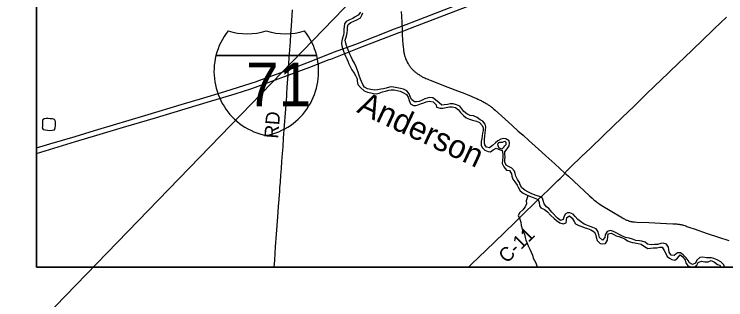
# Model space of a CAD drawing. Extents: x -49 to -8.2, y 9.4 to 23.5.
# Drawn here: x -46.335 to -44.886, y 14.138 to 14.718 of the extents above; entities that cross this region are included whole.
import ezdxf

# ---------------------------------------------------------------- set-up
doc = ezdxf.new("R2010")
doc.units = 0
for name, color, linetype in [('GM_X_Adjacent_County', 7, 'Continuous'), ('GM_X_County_Road', 7, 'Continuous'), ('GM_X_County_Road_Text', 7, 'Continuous'), ('GM_X_Interstate_Route', 7, 'Continuous'), ('GM_X_Interstate_Shield', 7, 'Continuous'), ('GM_X_Major_River', 7, 'Continuous'), ('GM_X_Major_River_Text', 7, 'Continuous'), ('GM_X_Minor_Lake', 7, 'Continuous'), ('GM_X_Minor_River', 7, 'Continuous'), ('GM_X_Township', 7, 'Continuous'), ('GM_X_Township_Road', 7, 'Continuous'), ('GM_X_Township_Road_Text', 7, 'Continuous'), ('SC_Scratch1', 7, 'Continuous')]:
    doc.layers.add(name, color=color, linetype=linetype)

msp = doc.modelspace()

# ---------------------------------------------------------------- linework, layer by layer
at = {"layer": 'GM_X_Adjacent_County'}
msp.add_lwpolyline([(-39.4895, 17.0861), (-39.4895, 14.2039), (-46.2895, 14.2039), (-46.2895, 15.4273)], dxfattribs=at)
at = {"layer": 'GM_X_County_Road'}
for points in [[(-45.5468, 14.7238), (-45.5464, 14.7141), (-45.5458, 14.7024), (-45.5453, 14.6944), (-45.5451, 14.6903), (-45.5447, 14.6835), (-45.5445, 14.6772), (-45.5439, 14.6664), (-45.5438, 14.6632), (-45.5436, 14.6604), (-45.5433, 14.6566), (-45.543, 14.6534), (-45.5427, 14.6505), (-45.5424, 14.6479), (-45.5422, 14.646), (-45.5419, 14.644), (-45.5416, 14.6421), (-45.5413, 14.6404), (-45.541, 14.6388), (-45.5406, 14.6373), (-45.5402, 14.6356), (-45.5398, 14.6341), (-45.5392, 14.6322), (-45.5387, 14.6308), (-45.5383, 14.6296), (-45.5377, 14.6279), (-45.5371, 14.6264), (-45.5363, 14.6246), (-45.5355, 14.6229), (-45.5346, 14.6211), (-45.5336, 14.6193), (-45.5327, 14.6177), (-45.532, 14.6167), (-45.5313, 14.6156), (-45.5303, 14.6141), (-45.5293, 14.6128), (-45.5282, 14.6113), (-45.5272, 14.61), (-45.5262, 14.6087), (-45.525, 14.6074), (-45.5241, 14.6064), (-45.5231, 14.6054), (-45.5221, 14.6043), (-45.521, 14.6033), (-45.52, 14.6023), (-45.5189, 14.6014), (-45.5178, 14.6005), (-45.5166, 14.5995), (-45.5151, 14.5984), (-45.5136, 14.5973), (-45.5122, 14.5964), (-45.511, 14.5956), (-45.5098, 14.5948), (-45.5085, 14.594), (-45.5071, 14.5932), (-45.5054, 14.5922), (-45.5038, 14.5913), (-45.5024, 14.5906), (-45.5007, 14.5897), (-45.4988, 14.5888), (-45.4964, 14.5878), (-45.494, 14.5868), (-45.4914, 14.5857), (-45.4881, 14.5844), (-45.4724, 14.5782), (-45.4605, 14.5736), (-45.4373, 14.5647), (-45.4174, 14.5569), (-45.4112, 14.5544), (-45.4059, 14.5523), (-45.4017, 14.5506), (-45.3995, 14.5497), (-45.397, 14.5486), (-45.3949, 14.5477), (-45.3928, 14.5468), (-45.3907, 14.5458), (-45.3891, 14.5451), (-45.3877, 14.5444), (-45.3861, 14.5436), (-45.3842, 14.5426), (-45.3825, 14.5417), (-45.3805, 14.5406), (-45.3783, 14.5394), (-45.3761, 14.5382), (-45.3741, 14.537), (-45.3725, 14.5361), (-45.3711, 14.5352), (-45.3696, 14.5343), (-45.3683, 14.5334), (-45.367, 14.5325), (-45.3658, 14.5317), (-45.3642, 14.5305), (-45.3629, 14.5295), (-45.3616, 14.5285), (-45.3601, 14.5273), (-45.3579, 14.5255), (-45.3556, 14.5235), (-45.3356, 14.5053), (-45.3204, 14.4916), (-45.3091, 14.4814), (-45.2986, 14.4721), (-45.2866, 14.4613), (-45.2742, 14.45), (-45.2606, 14.4377), (-45.2522, 14.4303), (-45.2343, 14.414), (-45.2133, 14.3952)], [(-45.2133, 14.3952), (-45.2127, 14.3959), (-45.2122, 14.3966), (-45.2115, 14.3975), (-45.2108, 14.3983), (-45.2101, 14.3991), (-45.2089, 14.4004), (-45.2074, 14.4018), (-45.2056, 14.4037), (-45.2018, 14.4074), (-45.1787, 14.4296), (-45.162, 14.4455), (-45.1348, 14.4718), (-45.0972, 14.508), (-45.0725, 14.5317), (-45.047, 14.5563), (-45.0314, 14.5714), (-45.0025, 14.5992), (-44.9805, 14.6203), (-44.9723, 14.6283), (-44.9518, 14.6482), (-44.9354, 14.6639), (-44.9101, 14.6882), (-44.896, 14.7018), (-44.8845, 14.7126)], [(-45.4097, 14.2039), (-45.4043, 14.2091), (-45.3872, 14.2258), (-45.3751, 14.2374), (-45.3549, 14.2568), (-45.3384, 14.2727), (-45.3299, 14.281), (-45.3224, 14.2883), (-45.315, 14.2955), (-45.3044, 14.3059), (-45.2907, 14.3191), (-45.2814, 14.3282), (-45.2735, 14.3359), (-45.2694, 14.34), (-45.2657, 14.3436), (-45.2624, 14.3467), (-45.2591, 14.3499), (-45.2554, 14.3534), (-45.2499, 14.3587), (-45.2365, 14.3716), (-45.2277, 14.38), (-45.2233, 14.3842), (-45.2205, 14.3868), (-45.219, 14.3884), (-45.2173, 14.3901), (-45.2165, 14.391), (-45.2157, 14.392), (-45.2149, 14.3929), (-45.2141, 14.394), (-45.2133, 14.3952)], [(-45.2133, 14.3952), (-45.211, 14.3931), (-45.2062, 14.3888), (-45.1956, 14.379), (-45.1634, 14.3491), (-45.1578, 14.3441), (-45.1544, 14.341), (-45.1523, 14.3393), (-45.1501, 14.3375), (-45.1484, 14.3361), (-45.1464, 14.3346), (-45.1445, 14.3333), (-45.1426, 14.3319), (-45.1399, 14.3302), (-45.1364, 14.3281), (-45.1214, 14.3193), (-45.0965, 14.3045), (-45.0941, 14.3032), (-45.0921, 14.302), (-45.0907, 14.3012), (-45.0893, 14.3005), (-45.0878, 14.2998), (-45.0866, 14.2992), (-45.085, 14.2986), (-45.0837, 14.2981), (-45.0828, 14.2977), (-45.0816, 14.2973), (-45.0802, 14.297), (-45.079, 14.2968), (-45.0774, 14.2965), (-45.0759, 14.2963), (-45.0737, 14.2961), (-45.0715, 14.2959), (-45.0671, 14.2957), (-45.0425, 14.2945), (-45.0066, 14.2929), (-44.9938, 14.2924), (-44.992, 14.2923), (-44.9901, 14.2922), (-44.9883, 14.2921), (-44.986, 14.2919), (-44.9839, 14.2917), (-44.9821, 14.2915), (-44.9807, 14.2913), (-44.9795, 14.291), (-44.9784, 14.2908), (-44.9769, 14.2905), (-44.9752, 14.2901), (-44.9738, 14.2897), (-44.972, 14.2892), (-44.9695, 14.2884), (-44.9674, 14.2877), (-44.965, 14.2869), (-44.9588, 14.2848), (-44.9505, 14.2819), (-44.9236, 14.2724), (-44.9005, 14.2647), (-44.8794, 14.258)]]:
    msp.add_lwpolyline(points, dxfattribs=at)
at = {"layer": 'GM_X_Interstate_Route'}
for points in [[(-45.6199, 14.6545), (-45.5512, 14.6809), (-45.5447, 14.6835), (-45.5277, 14.6902), (-45.4354, 14.7255), (-45.3554, 14.7563), (-45.2574, 14.7941), (-45.2, 14.8162), (-45.1231, 14.8457), (-45.0115, 14.8888), (-44.9338, 14.9187), (-44.8808, 14.9391), (-44.8112, 14.9659)], [(-46.2895, 14.4464), (-46.262, 14.4547), (-46.2104, 14.47), (-46.1712, 14.4818), (-46.1645, 14.484), (-46.1009, 14.5028), (-46.0687, 14.5123), (-45.9879, 14.5368), (-45.9554, 14.5464), (-45.906, 14.5611), (-45.8653, 14.5739), (-45.8414, 14.5817), (-45.8364, 14.5833), (-45.8078, 14.5937), (-45.7762, 14.6056), (-45.7264, 14.6245), (-45.6845, 14.641), (-45.6394, 14.6578), (-45.5604, 14.6886), (-45.5453, 14.6944), (-45.4293, 14.7391)], [(-45.6903, 14.6273), (-45.6324, 14.6497), (-45.6199, 14.6545)], [(-46.2895, 14.4353), (-46.2631, 14.4432), (-46.2096, 14.4592), (-46.1667, 14.4721), (-46.1122, 14.4884), (-46.0473, 14.5078), (-45.942, 14.5393), (-45.8846, 14.5567), (-45.8512, 14.5675), (-45.8251, 14.5766), (-45.8099, 14.5821), (-45.7769, 14.5941), (-45.7325, 14.6109), (-45.6932, 14.6262), (-45.6903, 14.6273)]]:
    msp.add_lwpolyline(points, dxfattribs=at)
at = {"layer": 'GM_X_Interstate_Shield'}
for p, q in [((-45.9239, 14.6345), (-45.7189, 14.6345)), ((-45.7189, 14.6345), (-45.9239, 14.6345)), ((-45.7189, 14.6345), (-45.9239, 14.6345))]:
    msp.add_line(p, q, dxfattribs=at)
for centre, start, end in [((-45.7947, 14.6019), 141.669, 165.8066), ((-45.8603, 14.8118), 253.0091, 286.9909), ((-45.7825, 14.8118), 253.0091, 286.9909), ((-45.848, 14.6019), 14.1934, 38.331), ((-45.7947, 14.6019), 165.8066, 258.463), ((-45.848, 14.6019), 281.537, 14.1934)]:
    msp.add_arc(centre, 0.1332, start, end, dxfattribs=at)
at = {"layer": 'GM_X_Major_River'}
for points in [[(-45.6296, 14.7227), (-45.6345, 14.7165), (-45.6402, 14.7131), (-45.6455, 14.71), (-45.6523, 14.707), (-45.6588, 14.7038), (-45.6622, 14.6987), (-45.6628, 14.6926), (-45.6634, 14.6879), (-45.6638, 14.6812), (-45.6643, 14.6757), (-45.666, 14.6704), (-45.6674, 14.6645), (-45.6682, 14.659), (-45.6678, 14.6543), (-45.6661, 14.6492), (-45.6642, 14.6431), (-45.6623, 14.6376), (-45.6602, 14.6329), (-45.6574, 14.6274), (-45.6555, 14.6226), (-45.6531, 14.6173), (-45.6501, 14.6108), (-45.6476, 14.605), (-45.6425, 14.5985), (-45.6397, 14.5938), (-45.6366, 14.5869), (-45.6363, 14.582), (-45.6351, 14.5757), (-45.6293, 14.5695), (-45.6223, 14.5626), (-45.6153, 14.5598), (-45.6088, 14.5583), (-45.603, 14.5573), (-45.5963, 14.5563), (-45.5914, 14.558), (-45.585, 14.5605), (-45.5785, 14.5616), (-45.5721, 14.5637), (-45.5673, 14.5646), (-45.5611, 14.5643), (-45.555, 14.5635), (-45.5486, 14.5616), (-45.5433, 14.5593), (-45.5363, 14.5549), (-45.5329, 14.55), (-45.5308, 14.5428)], [(-45.3771, 14.464), (-45.3767, 14.4703), (-45.3756, 14.4769), (-45.3752, 14.4828), (-45.3743, 14.4894), (-45.3756, 14.4949), (-45.3807, 14.5012), (-45.3858, 14.5033), (-45.3918, 14.5086), (-45.3994, 14.5115), (-45.4064, 14.5122), (-45.4129, 14.5157), (-45.4195, 14.5204), (-45.4231, 14.5261), (-45.4274, 14.5314), (-45.4342, 14.5339), (-45.4409, 14.5364), (-45.4469, 14.5358), (-45.4528, 14.5345), (-45.459, 14.5338), (-45.4638, 14.5332), (-45.4698, 14.5379), (-45.4766, 14.544), (-45.4825, 14.5484), (-45.4888, 14.5488), (-45.4939, 14.5478), (-45.4986, 14.5463), (-45.5039, 14.5437), (-45.5104, 14.5412), (-45.5153, 14.5403), (-45.52, 14.5399), (-45.5255, 14.5452), (-45.5283, 14.5513), (-45.5306, 14.5562), (-45.5353, 14.5623), (-45.5418, 14.5661), (-45.5482, 14.5676), (-45.5548, 14.5684), (-45.5658, 14.5707), (-45.5707, 14.5701), (-45.5772, 14.5681), (-45.5829, 14.5668), (-45.588, 14.5662), (-45.5952, 14.5647), (-45.6014, 14.5641), (-45.6083, 14.5655), (-45.6153, 14.5666), (-45.6215, 14.5698), (-45.6251, 14.5757), (-45.6279, 14.5818), (-45.6296, 14.5865), (-45.6323, 14.5936), (-45.6345, 14.6004), (-45.6364, 14.6057), (-45.6385, 14.6116), (-45.6421, 14.6188), (-45.6457, 14.6254), (-45.6487, 14.6317), (-45.6511, 14.637), (-45.6532, 14.6423), (-45.656, 14.6494), (-45.6581, 14.6549), (-45.6598, 14.6596), (-45.6606, 14.6657), (-45.6583, 14.6736), (-45.6566, 14.6805), (-45.6562, 14.6863), (-45.6563, 14.6926), (-45.6548, 14.6973), (-45.6495, 14.7017), (-45.6431, 14.7043), (-45.6368, 14.7072), (-45.6294, 14.7113), (-45.6271, 14.7164), (-45.625, 14.7214)], [(-45.5308, 14.5428), (-45.528, 14.5363), (-45.5217, 14.5325), (-45.517, 14.5325), (-45.5121, 14.5338), (-45.5056, 14.5369), (-45.5009, 14.5382), (-45.496, 14.5399), (-45.489, 14.5414), (-45.4816, 14.5402), (-45.4757, 14.5343), (-45.4746, 14.5296), (-45.4676, 14.5273), (-45.4619, 14.5271), (-45.4553, 14.5284), (-45.4484, 14.5303), (-45.4431, 14.5303), (-45.4365, 14.5286), (-45.4303, 14.5242), (-45.4261, 14.5187), (-45.4202, 14.5121), (-45.4144, 14.5077), (-45.4079, 14.5049), (-45.4013, 14.5029), (-45.3936, 14.5007), (-45.3871, 14.498), (-45.3818, 14.4921), (-45.3799, 14.4874), (-45.3801, 14.4822), (-45.3811, 14.4762), (-45.3819, 14.4712), (-45.3826, 14.4659), (-45.3838, 14.4593), (-45.384, 14.4521), (-45.3817, 14.4474), (-45.3762, 14.4417), (-45.37, 14.439), (-45.3652, 14.4384), (-45.3592, 14.4428), (-45.3533, 14.4458), (-45.3472, 14.4431), (-45.341, 14.441), (-45.3395, 14.4344), (-45.3399, 14.4283), (-45.3405, 14.4215), (-45.3409, 14.4147), (-45.3378, 14.4078), (-45.3322, 14.4014), (-45.3261, 14.4002), (-45.3219, 14.3938), (-45.3216, 14.3889), (-45.3193, 14.3826), (-45.3153, 14.3777), (-45.3104, 14.371), (-45.3078, 14.3653), (-45.3046, 14.3591), (-45.2987, 14.3543), (-45.293, 14.3518), (-45.2872, 14.349), (-45.2817, 14.3467), (-45.2749, 14.3444), (-45.2682, 14.3416), (-45.2658, 14.3353), (-45.265, 14.329), (-45.2622, 14.3243), (-45.255, 14.3211), (-45.2488, 14.3163), (-45.2431, 14.31), (-45.2355, 14.303), (-45.2306, 14.299), (-45.2238, 14.2941), (-45.2168, 14.2918), (-45.2111, 14.2941), (-45.2103, 14.2992), (-45.2098, 14.3051), (-45.2039, 14.3081), (-45.1986, 14.3033), (-45.1946, 14.2969), (-45.1916, 14.2921), (-45.1848, 14.2887), (-45.1793, 14.2864), (-45.174, 14.2847), (-45.1677, 14.2828), (-45.1604, 14.2798), (-45.1537, 14.276), (-45.1509, 14.2712), (-45.1496, 14.265), (-45.1477, 14.2581), (-45.1418, 14.2522), (-45.1364, 14.2511), (-45.1309, 14.252), (-45.1265, 14.2587), (-45.1261, 14.2653), (-45.1251, 14.2716), (-45.1196, 14.2731), (-45.114, 14.2702), (-45.1089, 14.2679), (-45.1036, 14.266), (-45.0983, 14.2645), (-45.0916, 14.2613), (-45.086, 14.2577)], [(-44.9252, 14.2231), (-44.9324, 14.224), (-44.9386, 14.2235), (-44.9451, 14.2182), (-44.9479, 14.2121), (-44.9534, 14.2095), (-44.9595, 14.2127), (-44.9623, 14.2176), (-44.9667, 14.2231), (-44.9725, 14.2287), (-44.9784, 14.2332), (-44.9845, 14.2334), (-44.9907, 14.2279), (-44.9973, 14.2283), (-45.0011, 14.2346), (-45.0017, 14.2395), (-45.0026, 14.2443), (-45.0068, 14.2507), (-45.0134, 14.2526), (-45.0181, 14.2519), (-45.025, 14.2498), (-45.031, 14.25), (-45.0379, 14.2496), (-45.045, 14.2508), (-45.05, 14.2549), (-45.0566, 14.2567), (-45.0619, 14.2572), (-45.0689, 14.2584), (-45.0757, 14.2612), (-45.0829, 14.263), (-45.0903, 14.2641), (-45.0964, 14.2673), (-45.1013, 14.2698), (-45.1079, 14.2729), (-45.1143, 14.2765), (-45.1208, 14.2786), (-45.1272, 14.2763), (-45.1314, 14.27), (-45.1325, 14.2644), (-45.1367, 14.2591), (-45.1428, 14.264), (-45.1443, 14.2699), (-45.1458, 14.2756), (-45.1496, 14.2818), (-45.1569, 14.2849), (-45.1621, 14.2864), (-45.1685, 14.2891), (-45.1742, 14.2917), (-45.1814, 14.2965), (-45.187, 14.3012), (-45.1929, 14.3069), (-45.1969, 14.3117), (-45.2031, 14.3145), (-45.2079, 14.3142), (-45.2126, 14.3119), (-45.2154, 14.3056), (-45.217, 14.3009), (-45.2223, 14.299), (-45.2283, 14.3039), (-45.2404, 14.3161), (-45.2463, 14.3233), (-45.251, 14.3269), (-45.2559, 14.3326), (-45.2574, 14.3395), (-45.2593, 14.3446), (-45.2652, 14.3474), (-45.2718, 14.3495), (-45.2773, 14.3514), (-45.2822, 14.3537), (-45.2889, 14.3571), (-45.2951, 14.3602), (-45.301, 14.3651), (-45.3046, 14.3712), (-45.3061, 14.3759), (-45.3097, 14.3824), (-45.3132, 14.3892), (-45.3144, 14.3942), (-45.3163, 14.3991), (-45.3212, 14.4052), (-45.328, 14.4086), (-45.3331, 14.4111), (-45.3355, 14.4177), (-45.3359, 14.4228), (-45.3353, 14.4287), (-45.3357, 14.4334), (-45.3355, 14.4384), (-45.3311, 14.4448), (-45.3271, 14.4505), (-45.326, 14.456), (-45.3271, 14.4609), (-45.3334, 14.4649), (-45.3385, 14.4655), (-45.3442, 14.4646), (-45.3497, 14.4611), (-45.3546, 14.4568), (-45.3611, 14.4511), (-45.3667, 14.4469), (-45.3734, 14.4479), (-45.3768, 14.453), (-45.3771, 14.4578), (-45.3771, 14.464)], [(-45.3381, 14.459), (-45.3415, 14.4577), (-45.3438, 14.4573), (-45.3467, 14.4572), (-45.3487, 14.4566), (-45.3508, 14.4543), (-45.3499, 14.4511), (-45.3478, 14.4467), (-45.3436, 14.4454), (-45.3414, 14.4448), (-45.3378, 14.4479), (-45.3355, 14.4507), (-45.3332, 14.4535)], [(-45.3332, 14.4535), (-45.3329, 14.4573), (-45.3335, 14.4584), (-45.3353, 14.4594), (-45.3357, 14.4595), (-45.3381, 14.459)], [(-45.086, 14.2577), (-45.0808, 14.2554), (-45.0759, 14.2538), (-45.0712, 14.2531), (-45.0646, 14.2521), (-45.0579, 14.2506), (-45.0515, 14.2457), (-45.0443, 14.2422), (-45.0394, 14.2424), (-45.0335, 14.243), (-45.0265, 14.2435), (-45.0202, 14.2445), (-45.0153, 14.2443), (-45.0112, 14.2378), (-45.0083, 14.2317), (-45.0053, 14.2259), (-45.0004, 14.2221), (-44.9955, 14.2196), (-44.9894, 14.2181), (-44.9843, 14.2224), (-44.9786, 14.2289), (-44.9731, 14.2247), (-44.9688, 14.218), (-44.9673, 14.2129), (-44.9631, 14.2065), (-44.9572, 14.2049), (-44.9512, 14.2039)], [(-44.9502, 14.2039), (-44.9447, 14.2081), (-44.9421, 14.2131), (-44.9352, 14.2159), (-44.9284, 14.2147), (-44.9216, 14.2149), (-44.9155, 14.2176), (-44.9087, 14.214), (-44.9029, 14.2094), (-44.8977, 14.2081), (-44.8963, 14.2039)], [(-44.8883, 14.2039), (-44.8902, 14.2088), (-44.8962, 14.2149), (-44.9038, 14.2191), (-44.9102, 14.2217), (-44.9153, 14.2227), (-44.9204, 14.2231), (-44.9252, 14.2231)]]:
    msp.add_lwpolyline(points, dxfattribs=at)
at = {"layer": 'GM_X_Minor_Lake'}
for points in [[(-46.2508, 14.4925), (-46.2507, 14.4959), (-46.2509, 14.5001), (-46.2527, 14.5045), (-46.2567, 14.5053), (-46.2612, 14.5056), (-46.2656, 14.5062), (-46.2695, 14.5063), (-46.2735, 14.5058), (-46.277, 14.503), (-46.2774, 14.4988), (-46.2771, 14.4943), (-46.2774, 14.4899)], [(-46.2774, 14.4899), (-46.2775, 14.4876), (-46.2756, 14.484), (-46.2713, 14.4831), (-46.2667, 14.4825), (-46.2624, 14.4821), (-46.2574, 14.4824), (-46.2529, 14.4834), (-46.2511, 14.4874), (-46.2508, 14.4912), (-46.2508, 14.4925)]]:
    msp.add_lwpolyline(points, dxfattribs=at)
at = {"layer": 'GM_X_Minor_River'}
msp.add_lwpolyline([(-45.2886, 14.3497), (-45.2902, 14.3452), (-45.292, 14.3388), (-45.2917, 14.3325), (-45.2941, 14.3263), (-45.2992, 14.3203), (-45.3051, 14.315), (-45.3088, 14.3092), (-45.305, 14.3016), (-45.3032, 14.2953), (-45.3024, 14.2888), (-45.3008, 14.2821), (-45.2989, 14.2772), (-45.2956, 14.2709), (-45.2942, 14.264), (-45.2928, 14.2588), (-45.291, 14.2539), (-45.2881, 14.2472), (-45.2846, 14.2405), (-45.2824, 14.2342), (-45.2797, 14.2281), (-45.2779, 14.2223), (-45.2755, 14.2176), (-45.2729, 14.2128), (-45.2706, 14.2065), (-45.2698, 14.2039)], dxfattribs=at)
at = {"layer": 'GM_X_Township'}
msp.add_lwpolyline([(-46.2895, 15.4273), (-46.2895, 14.2039), (-44.8206, 14.2039)], dxfattribs=at)
at = {"layer": 'GM_X_Township_Road'}
msp.add_lwpolyline([(-45.8051, 14.2039), (-45.8041, 14.2181), (-45.8024, 14.2454), (-45.8005, 14.2712), (-45.7993, 14.2885), (-45.7979, 14.3065), (-45.7963, 14.3275), (-45.7941, 14.3576), (-45.7936, 14.365), (-45.7927, 14.3771), (-45.7915, 14.3911), (-45.7905, 14.4044), (-45.7895, 14.4189), (-45.7882, 14.4354), (-45.7872, 14.449), (-45.7861, 14.4664), (-45.7841, 14.4924), (-45.7823, 14.5175), (-45.781, 14.5336), (-45.7805, 14.541), (-45.7796, 14.5547), (-45.7793, 14.5574), (-45.7786, 14.5692), (-45.7774, 14.5869), (-45.7769, 14.5941), (-45.7767, 14.5974), (-45.7762, 14.6056), (-45.7754, 14.6176), (-45.7747, 14.63), (-45.7724, 14.6622), (-45.7714, 14.6786), (-45.7704, 14.6944), (-45.7683, 14.7276)], dxfattribs=at)
at = {"layer": 'SC_Scratch1'}
msp.add_line((-48.2943, 12.0149), (-38.2371, 22.3973), dxfattribs=at)

# ---------------------------------------------------------------- texts
at = {"layer": 'GM_X_County_Road_Text'}
msp.add_text('C-11', height=0.02841, rotation=44.0343, dxfattribs=at).set_placement((-45.3319, 14.2105))
at = {"layer": 'GM_X_Interstate_Shield'}
msp.add_text('71', height=0.08878, dxfattribs=at).set_placement((-45.8624, 14.5313))
at = {"layer": 'GM_X_Major_River_Text'}
msp.add_text('Anderson', height=0.04735, rotation=335.0263, dxfattribs=at).set_placement((-45.6389, 14.5198))
at = {"layer": 'GM_X_Township_Road_Text'}
msp.add_text('RD', height=0.02841, rotation=85.6003, dxfattribs=at).set_placement((-45.7973, 14.4648))

doc.saveas('drawing.dxf')
